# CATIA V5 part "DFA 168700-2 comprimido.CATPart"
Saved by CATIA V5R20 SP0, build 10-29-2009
Part number: DFA 168700-2 comprimido
Revision: ANY
Definition: UNKNOWN
Nomenclature: DFA 168700-2 comprimido
Source: Unknown
Bounding box of the stored display mesh (mm): x -2.8 to 2.8, y 0 to 4.04, z -2.8 to 2.8
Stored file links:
  C:\Users\Utente\Desktop\IO LAVORO\3D X SITO CF\CUMSA\3D files FA\FA 168712-21\DFA 168700-2 comprimido.CATPart
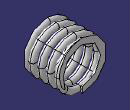
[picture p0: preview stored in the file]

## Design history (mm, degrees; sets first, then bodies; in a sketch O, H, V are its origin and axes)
Body1 "Cortar-Extruir1" (main body)
  Solid1: solid without history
